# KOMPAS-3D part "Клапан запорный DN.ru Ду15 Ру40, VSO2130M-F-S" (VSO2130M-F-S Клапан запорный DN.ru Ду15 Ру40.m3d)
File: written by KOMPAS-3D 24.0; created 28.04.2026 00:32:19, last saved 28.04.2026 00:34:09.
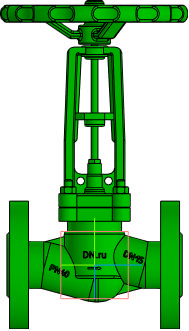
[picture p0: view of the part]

Document properties: Автор: DN.ru; Полное имя файла: C:\Работа\ГОТОВЫЕ ИСХОДНИКИ\VSO2130M-F-S Клапан запорный сильфонный DN.ru Ду15-100 Ру40\DN15\VSO2130M-F-S Клапан запорный DN.ru Ду15 Ру40.m3d

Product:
- Part/product: Клапан запорный DN.ru Ду15 Ру40  | designation VSO2130M-F-S
    Масса: 4
    Раздел спецификации: Прочие изделия
    Примечание: D090-01970

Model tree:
1. Операция без истории:1

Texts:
  VSO2130M-F-S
